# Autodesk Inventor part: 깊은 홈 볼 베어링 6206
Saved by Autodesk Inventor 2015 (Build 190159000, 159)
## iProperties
Created: 2025-06
Part Number: 깊은 홈 볼 베어링 6206
Material: 일반
Document SubType Name: Modeling
Designer: User
Density: 1 g/cm^3
Appearance: 기본값
Author: User
Author: jhkim
Description: 깊은 그루부 볼 베어링
Creation Date: 2025-05-23
Sending System: Autodesk Inventor 2026
Preprocessor: ST-DEVELOPER v20.1
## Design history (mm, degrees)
node "깊은 홈 볼 베어링 62061"
body "Solid1"
node "Solid1_1"
node "Solid1_2"
node "Solid1_3"
node "Solid1_4"
node "Solid1_5"
node "Solid1_6"
node "Solid1_7"
node "Solid1_8"
node "Solid1_9"
node "Solid1_10"
node "기준1"
node "기준2"
node "기준3"
node "기준4"
node "기준5"
node "기준6"
node "기준7"
node "기준8"
node "기준9"
node "기준10"
node "기준11"
